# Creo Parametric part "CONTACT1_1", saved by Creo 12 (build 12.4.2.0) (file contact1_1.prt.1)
Units: Custom; MM, KILOGRAM, SECS

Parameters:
  PTC_WM_ITERATION = "0"
  PTC_WM_VERSION = "-.0"
  PTC_WM_LIFECYCLE_STATE = "In Work"
  PTC_WM_LIFECYCLE = "MO_CADDocument"
  PTC_WM_CREATED_BY = "Maximilian Roepper (Z0017RMS: MO)"
  PTC_WM_CREATED_ON = "18-Sep-26 11:36:42 AM"
  PTC_WM_MODIFIED_BY = "Maximilian Roepper (Z0017RMS: MO)"
  PTC_WM_MODIFIED_ON = "18-Sep-26 11:36:46 AM"
  PDMLINKNUMBER = "PDM000071455211"
  PTC_WM_NAME = "contact1_1.prt"
  PTC_WM_NUMBER = "PDM000071455211"

Other parameters: WEIGHT, WEIGHT_FACTOR, WEIGHT_ADD, _MASS_TEMP, _DIFF_TEMP, MC_ERRORS, SUPPLIER

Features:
  1. coordinate system
  2. datum plane "PRT_YZ"
  3. datum plane "PRT_XY"
  4. datum plane "PRT_XZ"
  5. coordinate system
  6. datum axis
  7. datum axis
  8. datum axis
  9. coordinate system
  10. imported feature

Other named items: PRT, SIEMENS_MO, DRW_VIEW_ORG, PRT_X, PRT_Y, PRT_Z, CS0, ROUGH_GROB

Layers: 00_STD_CSYS-KSYS, 01_STD_PLANES-EBENEN, 02_STD_AXES-ACHSEN, 03_STD_CSYS-KSYS, 24_IMPORT_FEAT-IMPORT_KE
